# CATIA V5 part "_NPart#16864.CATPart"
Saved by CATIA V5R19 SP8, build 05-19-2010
Part number: Pièce10
Revision: ANY
Definition: UNKNOWN
Nomenclature: Pièce10
Source: Unknown
Bounding box of the stored display mesh (mm): x 0 to 4.5, y -4 to 4, z -3.991 to 3.991
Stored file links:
  D:\Documents\1_Travail\1 - ac-limoges.fr\ac-limoges.fr\Emmanuel Maynard - STI2D_Turgot\2 -2I2D\2_SEQUENCE_Serrure_Biométrique\5-Spé_ITEC\Serrure_Bio_Eleve\_NPart#16864.CATPart
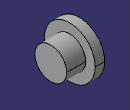
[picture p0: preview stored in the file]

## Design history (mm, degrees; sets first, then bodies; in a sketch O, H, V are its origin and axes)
Body1 "Révolution1" (main body)
  Solid1: solid without history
